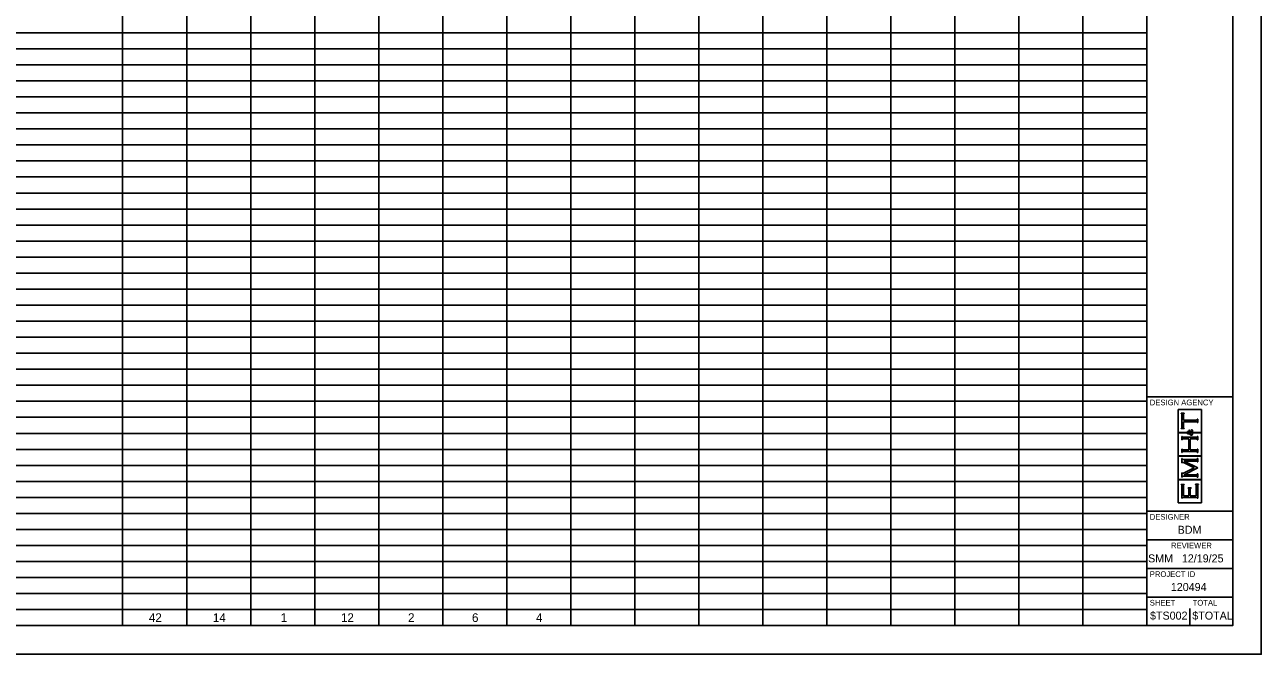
# Model space of a CAD drawing. Extents: x 0 to 34, y 0 to 22.
# Drawn here: x 12.37 to 34, y 0 to 11 of the extents above; entities that cross this region are included whole.
import ezdxf

# ---------------------------------------------------------------- set-up
doc = ezdxf.new("R2010")
doc.units = 0
for name, color, linetype in [('SH_Border', 7, 'Continuous'), ('SH_Cut_Line', 7, 'Continuous'), ('SH_Data', 7, 'Continuous'), ('SH_Text', 7, 'Continuous')]:
    doc.layers.add(name, color=color, linetype=linetype)

msp = doc.modelspace()

# ---------------------------------------------------------------- linework, layer by layer
at = {"layer": 'SH_Border'}
for p, q in [((32, 0.5), (32, 21.5)), ((32, 4.5), (33.5, 4.5)), ((32, 2.5), (33.5, 2.5)), ((32, 2), (33.5, 2)), ((32, 1.5), (33.5, 1.5)), ((32, 1), (33.5, 1))]:
    msp.add_line(p, q, dxfattribs=at)
msp.add_lwpolyline([(1.5, 21.5), (33.5, 21.5), (33.5, 0.5), (1.5, 0.5)], close=True, dxfattribs=at)
at = {"layer": 'SH_Cut_Line'}
msp.add_lwpolyline([(0, 0), (34, 0), (34, 22), (0, 22)], close=True, dxfattribs=at)
at = {"layer": 'SH_Data'}
for p, q in [((32.952, 4.279), (32.547, 4.279)), ((32.547, 4.279), (32.547, 3.875)), ((32.598, 4.204), (32.598, 4.211)), ((32.598, 4.211), (32.65, 4.211)), ((32.603, 4.203), (32.598, 4.204)), ((32.606, 4.201), (32.603, 4.203)), ((32.608, 4.199), (32.606, 4.201)), ((32.61, 4.196), (32.608, 4.199)), ((32.611, 4.192), (32.61, 4.196)), ((32.611, 4.187), (32.611, 4.192)), ((32.611, 3.968), (32.611, 4.187)), ((32.638, 4.196), (32.637, 4.192)), ((32.637, 4.192), (32.637, 4.187)), ((32.637, 4.187), (32.637, 4.093)), ((32.64, 4.199), (32.638, 4.196)), ((32.642, 4.201), (32.64, 4.199)), ((32.645, 4.203), (32.642, 4.201)), ((32.65, 4.204), (32.645, 4.203)), ((32.65, 4.211), (32.65, 4.204)), ((32.952, 3.875), (32.952, 4.279)), ((32.598, 3.95), (32.603, 3.951)), ((32.598, 3.944), (32.598, 3.95)), ((32.65, 3.944), (32.598, 3.944)), ((32.603, 3.951), (32.606, 3.953)), ((32.606, 3.953), (32.608, 3.955)), ((32.608, 3.955), (32.61, 3.958)), ((32.61, 3.958), (32.611, 3.962)), ((32.611, 3.962), (32.611, 3.968)), ((32.637, 4.093), (32.864, 4.093)), ((32.864, 4.061), (32.637, 4.061)), ((32.637, 4.061), (32.637, 3.968)), ((32.637, 3.968), (32.637, 3.962)), ((32.637, 3.962), (32.638, 3.958)), ((32.638, 3.958), (32.64, 3.955)), ((32.64, 3.955), (32.642, 3.953)), ((32.642, 3.953), (32.645, 3.951)), ((32.645, 3.951), (32.65, 3.95)), ((32.65, 3.95), (32.65, 3.944)), ((32.738, 3.893), (32.738, 3.922)), ((32.738, 3.922), (32.741, 3.922)), ((32.741, 3.922), (32.741, 3.918)), ((32.741, 3.918), (32.742, 3.915)), ((32.742, 3.896), (32.741, 3.895)), ((32.741, 3.895), (32.741, 3.893)), ((32.742, 3.915), (32.743, 3.913)), ((32.743, 3.897), (32.742, 3.896)), ((32.743, 3.913), (32.745, 3.911)), ((32.745, 3.899), (32.743, 3.897)), ((32.745, 3.911), (32.749, 3.908)), ((32.746, 3.899), (32.745, 3.899)), ((32.748, 3.899), (32.746, 3.899)), ((32.755, 3.899), (32.748, 3.899)), ((32.749, 3.908), (32.756, 3.904)), ((32.763, 3.895), (32.755, 3.899)), ((32.756, 3.904), (32.763, 3.9)), ((32.763, 3.9), (32.77, 3.896)), ((32.772, 3.887), (32.763, 3.895)), ((32.77, 3.896), (32.776, 3.891)), ((32.776, 3.891), (32.781, 3.895)), ((32.779, 3.923), (32.781, 3.926)), ((32.782, 3.922), (32.779, 3.923)), ((32.781, 3.926), (32.787, 3.924)), ((32.781, 3.895), (32.784, 3.898)), ((32.785, 3.921), (32.782, 3.922)), ((32.784, 3.898), (32.786, 3.901)), ((32.786, 3.919), (32.785, 3.921)), ((32.788, 3.917), (32.786, 3.919)), ((32.786, 3.901), (32.788, 3.904)), ((32.787, 3.924), (32.792, 3.921)), ((32.789, 3.914), (32.788, 3.917)), ((32.788, 3.904), (32.789, 3.908)), ((32.789, 3.911), (32.789, 3.914)), ((32.789, 3.908), (32.789, 3.911)), ((32.792, 3.921), (32.795, 3.918)), ((32.795, 3.918), (32.798, 3.914)), ((32.798, 3.897), (32.796, 3.894)), ((32.798, 3.914), (32.799, 3.91)), ((32.799, 3.901), (32.798, 3.897)), ((32.799, 3.91), (32.799, 3.905)), ((32.799, 3.905), (32.799, 3.901)), ((32.864, 4.093), (32.869, 4.093)), ((32.87, 4.061), (32.864, 4.061)), ((32.869, 4.093), (32.873, 4.094)), ((32.874, 4.06), (32.87, 4.061)), ((32.873, 4.094), (32.876, 4.096)), ((32.876, 4.059), (32.874, 4.06)), ((32.876, 4.096), (32.878, 4.097)), ((32.878, 4.057), (32.876, 4.059)), ((32.878, 4.097), (32.88, 4.101)), ((32.88, 4.053), (32.878, 4.057)), ((32.88, 4.101), (32.881, 4.106)), ((32.881, 4.048), (32.88, 4.053)), ((32.881, 4.106), (32.888, 4.106)), ((32.888, 4.048), (32.881, 4.048)), ((32.888, 4.106), (32.888, 4.048)), ((32.547, 3.875), (32.696, 3.875)), ((32.696, 3.869), (32.547, 3.869)), ((32.547, 3.869), (32.547, 3.465)), ((32.611, 3.749), (32.611, 3.807)), ((32.611, 3.807), (32.617, 3.807)), ((32.617, 3.749), (32.611, 3.749)), ((32.617, 3.807), (32.619, 3.802)), ((32.618, 3.754), (32.617, 3.749)), ((32.62, 3.758), (32.618, 3.754)), ((32.619, 3.802), (32.62, 3.798)), ((32.62, 3.798), (32.623, 3.797)), ((32.623, 3.76), (32.62, 3.758)), ((32.623, 3.797), (32.625, 3.795)), ((32.625, 3.761), (32.623, 3.76)), ((32.625, 3.795), (32.629, 3.794)), ((32.629, 3.762), (32.625, 3.761)), ((32.629, 3.794), (32.635, 3.794)), ((32.635, 3.762), (32.629, 3.762)), ((32.635, 3.794), (32.864, 3.794)), ((32.732, 3.762), (32.635, 3.762)), ((32.696, 3.875), (32.696, 3.869)), ((32.703, 3.879), (32.705, 3.883)), ((32.703, 3.873), (32.703, 3.879)), ((32.703, 3.868), (32.703, 3.873)), ((32.705, 3.863), (32.703, 3.868)), ((32.705, 3.883), (32.708, 3.887)), ((32.708, 3.858), (32.705, 3.863)), ((32.708, 3.887), (32.711, 3.89)), ((32.709, 3.879), (32.708, 3.876)), ((32.708, 3.876), (32.708, 3.873)), ((32.708, 3.873), (32.708, 3.869)), ((32.708, 3.869), (32.71, 3.866)), ((32.712, 3.853), (32.708, 3.858)), ((32.712, 3.881), (32.709, 3.879)), ((32.71, 3.866), (32.712, 3.864)), ((32.711, 3.89), (32.715, 3.892)), ((32.714, 3.883), (32.712, 3.881)), ((32.712, 3.864), (32.715, 3.862)), ((32.718, 3.85), (32.712, 3.853)), ((32.716, 3.884), (32.714, 3.883)), ((32.715, 3.892), (32.72, 3.892)), ((32.715, 3.862), (32.718, 3.861)), ((32.72, 3.884), (32.716, 3.884)), ((32.718, 3.861), (32.721, 3.861)), ((32.726, 3.85), (32.718, 3.85)), ((32.72, 3.892), (32.725, 3.892)), ((32.724, 3.884), (32.72, 3.884)), ((32.721, 3.861), (32.723, 3.861)), ((32.723, 3.861), (32.725, 3.862)), ((32.728, 3.882), (32.724, 3.884)), ((32.725, 3.892), (32.729, 3.89)), ((32.725, 3.862), (32.728, 3.862)), ((32.729, 3.85), (32.726, 3.85)), ((32.731, 3.88), (32.728, 3.882)), ((32.728, 3.862), (32.731, 3.863)), ((32.729, 3.89), (32.732, 3.887)), ((32.731, 3.85), (32.729, 3.85)), ((32.734, 3.877), (32.731, 3.88)), ((32.731, 3.863), (32.735, 3.865)), ((32.734, 3.851), (32.731, 3.85)), ((32.732, 3.887), (32.736, 3.883)), ((32.732, 3.572), (32.732, 3.762)), ((32.737, 3.872), (32.734, 3.877)), ((32.737, 3.852), (32.734, 3.851)), ((32.735, 3.865), (32.74, 3.867)), ((32.736, 3.883), (32.74, 3.878)), ((32.74, 3.867), (32.737, 3.872)), ((32.741, 3.853), (32.737, 3.852)), ((32.741, 3.893), (32.738, 3.893)), ((32.74, 3.878), (32.744, 3.869)), ((32.746, 3.855), (32.741, 3.853)), ((32.744, 3.869), (32.754, 3.875)), ((32.752, 3.844), (32.746, 3.855)), ((32.756, 3.86), (32.751, 3.857)), ((32.751, 3.857), (32.754, 3.852)), ((32.757, 3.837), (32.752, 3.844)), ((32.754, 3.875), (32.764, 3.881)), ((32.754, 3.852), (32.757, 3.848)), ((32.761, 3.863), (32.756, 3.86)), ((32.757, 3.848), (32.761, 3.845)), ((32.763, 3.833), (32.757, 3.837)), ((32.864, 3.762), (32.759, 3.762)), ((32.759, 3.762), (32.759, 3.572)), ((32.764, 3.865), (32.761, 3.863)), ((32.761, 3.845), (32.765, 3.843)), ((32.768, 3.829), (32.763, 3.833)), ((32.764, 3.881), (32.772, 3.887)), ((32.768, 3.867), (32.764, 3.865)), ((32.765, 3.843), (32.769, 3.841)), ((32.774, 3.872), (32.768, 3.867)), ((32.774, 3.827), (32.768, 3.829)), ((32.769, 3.841), (32.773, 3.841)), ((32.773, 3.841), (32.778, 3.841)), ((32.782, 3.878), (32.774, 3.872)), ((32.779, 3.827), (32.774, 3.827)), ((32.778, 3.841), (32.782, 3.843)), ((32.785, 3.827), (32.779, 3.827)), ((32.786, 3.873), (32.782, 3.878)), ((32.782, 3.843), (32.786, 3.846)), ((32.79, 3.829), (32.785, 3.827)), ((32.791, 3.886), (32.786, 3.881)), ((32.786, 3.881), (32.791, 3.876)), ((32.788, 3.869), (32.786, 3.873)), ((32.786, 3.846), (32.789, 3.849)), ((32.79, 3.867), (32.788, 3.869)), ((32.789, 3.849), (32.791, 3.853)), ((32.791, 3.864), (32.79, 3.867)), ((32.793, 3.834), (32.79, 3.829)), ((32.794, 3.89), (32.791, 3.886)), ((32.791, 3.876), (32.795, 3.87)), ((32.791, 3.861), (32.791, 3.864)), ((32.791, 3.859), (32.791, 3.861)), ((32.791, 3.853), (32.791, 3.859)), ((32.797, 3.838), (32.793, 3.834)), ((32.796, 3.894), (32.794, 3.89)), ((32.795, 3.87), (32.797, 3.866)), ((32.797, 3.866), (32.798, 3.861)), ((32.799, 3.844), (32.797, 3.838)), ((32.798, 3.861), (32.799, 3.857)), ((32.803, 3.869), (32.799, 3.875)), ((32.799, 3.875), (32.952, 3.875)), ((32.799, 3.857), (32.799, 3.852)), ((32.799, 3.852), (32.799, 3.844)), ((32.952, 3.869), (32.803, 3.869)), ((32.864, 3.794), (32.869, 3.794)), ((32.87, 3.762), (32.864, 3.762)), ((32.869, 3.794), (32.873, 3.795)), ((32.874, 3.761), (32.87, 3.762)), ((32.873, 3.795), (32.876, 3.797)), ((32.876, 3.76), (32.874, 3.761)), ((32.876, 3.797), (32.878, 3.798)), ((32.878, 3.758), (32.876, 3.76)), ((32.878, 3.798), (32.88, 3.802)), ((32.88, 3.754), (32.878, 3.758)), ((32.88, 3.802), (32.881, 3.807)), ((32.881, 3.749), (32.88, 3.754)), ((32.881, 3.807), (32.888, 3.807)), ((32.888, 3.749), (32.881, 3.749)), ((32.888, 3.807), (32.888, 3.749)), ((32.952, 3.465), (32.952, 3.869)), ((32.547, 3.465), (32.952, 3.465)), ((32.611, 3.527), (32.611, 3.585)), ((32.611, 3.585), (32.617, 3.585)), ((32.617, 3.527), (32.611, 3.527)), ((32.617, 3.585), (32.619, 3.58)), ((32.618, 3.532), (32.617, 3.527)), ((32.62, 3.536), (32.618, 3.532)), ((32.619, 3.58), (32.62, 3.576)), ((32.62, 3.576), (32.623, 3.574)), ((32.623, 3.537), (32.62, 3.536)), ((32.623, 3.574), (32.625, 3.573)), ((32.625, 3.539), (32.623, 3.537)), ((32.625, 3.573), (32.629, 3.572)), ((32.629, 3.54), (32.625, 3.539)), ((32.629, 3.572), (32.635, 3.572)), ((32.635, 3.54), (32.629, 3.54)), ((32.635, 3.572), (32.732, 3.572)), ((32.864, 3.54), (32.635, 3.54)), ((32.75, 3.5), (32.75, 3.5)), ((32.759, 3.572), (32.864, 3.572)), ((32.864, 3.572), (32.87, 3.572)), ((32.87, 3.54), (32.864, 3.54)), ((32.87, 3.572), (32.874, 3.573)), ((32.874, 3.539), (32.87, 3.54)), ((32.874, 3.573), (32.876, 3.574)), ((32.876, 3.538), (32.874, 3.539)), ((32.876, 3.574), (32.878, 3.576)), ((32.878, 3.536), (32.876, 3.538)), ((32.878, 3.576), (32.88, 3.58)), ((32.88, 3.532), (32.878, 3.536)), ((32.88, 3.58), (32.881, 3.585)), ((32.881, 3.527), (32.88, 3.532)), ((32.881, 3.585), (32.888, 3.585)), ((32.888, 3.527), (32.881, 3.527)), ((32.888, 3.585), (32.888, 3.527)), ((32.952, 3.459), (32.547, 3.459)), ((32.547, 3.459), (32.547, 3.055)), ((32.611, 3.345), (32.611, 3.418)), ((32.611, 3.418), (32.617, 3.418)), ((32.617, 3.345), (32.611, 3.345)), ((32.617, 3.418), (32.619, 3.412)), ((32.62, 3.352), (32.617, 3.345)), ((32.619, 3.412), (32.62, 3.409)), ((32.62, 3.409), (32.623, 3.407)), ((32.622, 3.355), (32.62, 3.352)), ((32.626, 3.355), (32.622, 3.355)), ((32.623, 3.407), (32.625, 3.405)), ((32.625, 3.405), (32.629, 3.405)), ((32.629, 3.355), (32.626, 3.355)), ((32.629, 3.405), (32.635, 3.405)), ((32.633, 3.353), (32.629, 3.355)), ((32.64, 3.35), (32.633, 3.353)), ((32.635, 3.405), (32.864, 3.405)), ((32.825, 3.257), (32.64, 3.35)), ((32.641, 3.165), (32.825, 3.257)), ((32.864, 3.373), (32.654, 3.373)), ((32.654, 3.373), (32.888, 3.255)), ((32.888, 3.255), (32.654, 3.138)), ((32.864, 3.405), (32.869, 3.405)), ((32.87, 3.373), (32.864, 3.373)), ((32.869, 3.405), (32.873, 3.405)), ((32.874, 3.372), (32.87, 3.373)), ((32.873, 3.405), (32.876, 3.407)), ((32.876, 3.37), (32.874, 3.372)), ((32.876, 3.407), (32.878, 3.409)), ((32.878, 3.369), (32.876, 3.37)), ((32.878, 3.409), (32.88, 3.412)), ((32.88, 3.365), (32.878, 3.369)), ((32.88, 3.412), (32.881, 3.418)), ((32.881, 3.36), (32.88, 3.365)), ((32.881, 3.418), (32.888, 3.418)), ((32.888, 3.36), (32.881, 3.36)), ((32.888, 3.418), (32.888, 3.36)), ((32.952, 3.055), (32.952, 3.459)), ((32.547, 3.055), (32.952, 3.055)), ((32.952, 3.049), (32.547, 3.049)), ((32.547, 3.049), (32.547, 2.645)), ((32.611, 3.096), (32.611, 3.168)), ((32.611, 3.168), (32.617, 3.168)), ((32.617, 3.096), (32.611, 3.096)), ((32.617, 3.168), (32.62, 3.162)), ((32.618, 3.102), (32.617, 3.096)), ((32.62, 3.105), (32.618, 3.102)), ((32.62, 3.162), (32.622, 3.158)), ((32.623, 3.107), (32.62, 3.105)), ((32.622, 3.158), (32.626, 3.158)), ((32.625, 3.109), (32.623, 3.107)), ((32.629, 3.109), (32.625, 3.109)), ((32.626, 3.158), (32.627, 3.158)), ((32.627, 3.158), (32.633, 3.161)), ((32.635, 3.109), (32.629, 3.109)), ((32.633, 3.161), (32.641, 3.165)), ((32.864, 3.109), (32.635, 3.109)), ((32.654, 3.138), (32.864, 3.138)), ((32.864, 3.138), (32.869, 3.138)), ((32.87, 3.109), (32.864, 3.109)), ((32.869, 3.138), (32.873, 3.139)), ((32.874, 3.109), (32.87, 3.109)), ((32.873, 3.139), (32.876, 3.141)), ((32.876, 3.107), (32.874, 3.109)), ((32.876, 3.141), (32.878, 3.143)), ((32.878, 3.105), (32.876, 3.107)), ((32.878, 3.143), (32.88, 3.146)), ((32.88, 3.102), (32.878, 3.105)), ((32.88, 3.146), (32.881, 3.151)), ((32.881, 3.096), (32.88, 3.102)), ((32.881, 3.151), (32.888, 3.151)), ((32.888, 3.096), (32.881, 3.096)), ((32.888, 3.151), (32.888, 3.096)), ((32.952, 2.645), (32.952, 3.049)), ((32.598, 2.962), (32.598, 2.969)), ((32.598, 2.969), (32.65, 2.969)), ((32.603, 2.961), (32.598, 2.962)), ((32.606, 2.959), (32.603, 2.961)), ((32.608, 2.957), (32.606, 2.959)), ((32.61, 2.955), (32.608, 2.957)), ((32.611, 2.951), (32.61, 2.955)), ((32.611, 2.945), (32.611, 2.951)), ((32.611, 2.725), (32.611, 2.945)), ((32.64, 2.957), (32.638, 2.955)), ((32.638, 2.955), (32.638, 2.951)), ((32.638, 2.951), (32.638, 2.945)), ((32.638, 2.945), (32.638, 2.77)), ((32.642, 2.959), (32.64, 2.957)), ((32.645, 2.961), (32.642, 2.959)), ((32.65, 2.962), (32.645, 2.961)), ((32.65, 2.969), (32.65, 2.962)), ((32.719, 2.902), (32.719, 2.908)), ((32.719, 2.908), (32.772, 2.908)), ((32.724, 2.901), (32.719, 2.902)), ((32.728, 2.899), (32.724, 2.901)), ((32.729, 2.896), (32.728, 2.899)), ((32.731, 2.894), (32.729, 2.896)), ((32.732, 2.89), (32.731, 2.894)), ((32.732, 2.884), (32.732, 2.89)), ((32.732, 2.77), (32.732, 2.884)), ((32.76, 2.894), (32.759, 2.89)), ((32.759, 2.89), (32.759, 2.884)), ((32.759, 2.884), (32.759, 2.77)), ((32.761, 2.896), (32.76, 2.894)), ((32.763, 2.899), (32.761, 2.896)), ((32.767, 2.901), (32.763, 2.899)), ((32.772, 2.902), (32.767, 2.901)), ((32.772, 2.908), (32.772, 2.902)), ((32.848, 2.965), (32.848, 2.972)), ((32.848, 2.972), (32.901, 2.972)), ((32.853, 2.964), (32.848, 2.965)), ((32.857, 2.962), (32.853, 2.964)), ((32.859, 2.96), (32.857, 2.962)), ((32.86, 2.958), (32.859, 2.96)), ((32.861, 2.953), (32.86, 2.958)), ((32.861, 2.948), (32.861, 2.953)), ((32.861, 2.77), (32.861, 2.948)), ((32.889, 2.957), (32.888, 2.953)), ((32.888, 2.953), (32.888, 2.948)), ((32.888, 2.948), (32.888, 2.725)), ((32.891, 2.96), (32.889, 2.957)), ((32.892, 2.962), (32.891, 2.96)), ((32.896, 2.964), (32.892, 2.962)), ((32.901, 2.965), (32.896, 2.964)), ((32.901, 2.972), (32.901, 2.965)), ((32.547, 2.645), (32.952, 2.645)), ((32.617, 2.725), (32.611, 2.725)), ((32.619, 2.73), (32.617, 2.725)), ((32.62, 2.734), (32.619, 2.73)), ((32.623, 2.735), (32.62, 2.734)), ((32.625, 2.737), (32.623, 2.735)), ((32.629, 2.738), (32.625, 2.737)), ((32.635, 2.738), (32.629, 2.738)), ((32.864, 2.738), (32.635, 2.738)), ((32.638, 2.77), (32.732, 2.77)), ((32.759, 2.77), (32.861, 2.77)), ((32.87, 2.738), (32.864, 2.738)), ((32.874, 2.737), (32.87, 2.738)), ((32.876, 2.735), (32.874, 2.737)), ((32.878, 2.734), (32.876, 2.735)), ((32.88, 2.73), (32.878, 2.734)), ((32.881, 2.725), (32.88, 2.73)), ((32.888, 2.725), (32.881, 2.725)), ((32.375, 0.675), (32.375, 0.675)), ((32.75, 0.5), (32.75, 0.8))]:
    msp.add_line(p, q, dxfattribs=at)
at = {"layer": 'SH_Text'}
for p, q in [((14.082, 21.5), (14.082, 0.5)), ((15.202, 21.5), (15.202, 0.5)), ((16.322, 21.5), (16.322, 0.5)), ((17.442, 21.5), (17.442, 0.5)), ((18.562, 21.5), (18.562, 0.5)), ((19.681, 21.5), (19.681, 0.5)), ((20.801, 21.5), (20.801, 0.5)), ((21.921, 21.5), (21.921, 0.5)), ((23.041, 21.5), (23.041, 0.5)), ((24.161, 21.5), (24.161, 0.5)), ((25.281, 21.5), (25.281, 0.5)), ((26.401, 21.5), (26.401, 0.5)), ((27.521, 21.5), (27.521, 0.5)), ((28.64, 21.5), (28.64, 0.5)), ((29.76, 21.5), (29.76, 0.5)), ((30.88, 21.5), (30.88, 0.5)), ((32, 21.5), (32, 0.5)), ((1.5, 10.86), (32, 10.86)), ((1.5, 10.58), (32, 10.58)), ((1.5, 10.3), (32, 10.3)), ((1.5, 10.02), (32, 10.02)), ((1.5, 9.74), (32, 9.74)), ((1.5, 9.46), (32, 9.46)), ((1.5, 9.18), (32, 9.18)), ((1.5, 8.9), (32, 8.9)), ((1.5, 8.62), (32, 8.62)), ((1.5, 8.34), (32, 8.34)), ((1.5, 8.06), (32, 8.06)), ((1.5, 7.78), (32, 7.78)), ((1.5, 7.5), (32, 7.5)), ((1.5, 7.22), (32, 7.22)), ((1.5, 6.94), (32, 6.94)), ((1.5, 6.66), (32, 6.66)), ((1.5, 6.38), (32, 6.38)), ((1.5, 6.1), (32, 6.1)), ((1.5, 5.82), (32, 5.82)), ((1.5, 5.54), (32, 5.54)), ((1.5, 5.26), (32, 5.26)), ((1.5, 4.98), (32, 4.98)), ((1.5, 4.7), (32, 4.7)), ((1.5, 4.42), (32, 4.42)), ((1.5, 4.14), (32, 4.14)), ((1.5, 3.86), (32, 3.86)), ((1.5, 3.58), (32, 3.58)), ((1.5, 3.3), (32, 3.3)), ((1.5, 3.02), (32, 3.02)), ((1.5, 2.74), (32, 2.74)), ((1.5, 2.46), (32, 2.46)), ((1.5, 2.18), (32, 2.18)), ((1.5, 1.9), (32, 1.9)), ((1.5, 1.62), (32, 1.62)), ((1.5, 1.34), (32, 1.34)), ((1.5, 1.06), (32, 1.06)), ((1.5, 0.78), (32, 0.78)), ((1.5, 0.5), (32, 0.5))]:
    msp.add_line(p, q, dxfattribs=at)

# ---------------------------------------------------------------- texts
at = {"layer": 'SH_Data'}
for s, height, p in [('DESIGN AGENCY', 0.1, (32.05, 4.35)), ('DESIGNER', 0.1, (32.05, 2.35)), ('BDM', 0.14, (32.537, 2.105)), ('REVIEWER', 0.1, (32.422, 1.85)), ('SMM', 0.14, (32.02, 1.605)), ('12/19/25', 0.14, (32.611, 1.605)), ('PROJECT ID', 0.1, (32.05, 1.35)), ('120494', 0.14, (32.418, 1.105)), ('SHEET', 0.1, (32.05, 0.85)), ('TOTAL', 0.1, (32.8, 0.85)), ('$TS002', 0.14, (32.054, 0.605)), ('$TOTAL', 0.14, (32.794, 0.605))]:
    msp.add_text(s, height=height, dxfattribs=at).set_placement(p)
at = {"layer": 'SH_Text'}
for s, height, p in [('42', 0.1515, (14.541, 0.564)), ('14', 0.1515, (15.661, 0.564)), ('1', 0.152, (16.846, 0.564)), ('12', 0.1515, (17.901, 0.564)), ('2', 0.152, (19.074, 0.564)), ('6', 0.152, (20.193, 0.564)), ('4', 0.152, (21.313, 0.564))]:
    msp.add_text(s, height=height, dxfattribs=at).set_placement(p)

doc.saveas('drawing.dxf')
